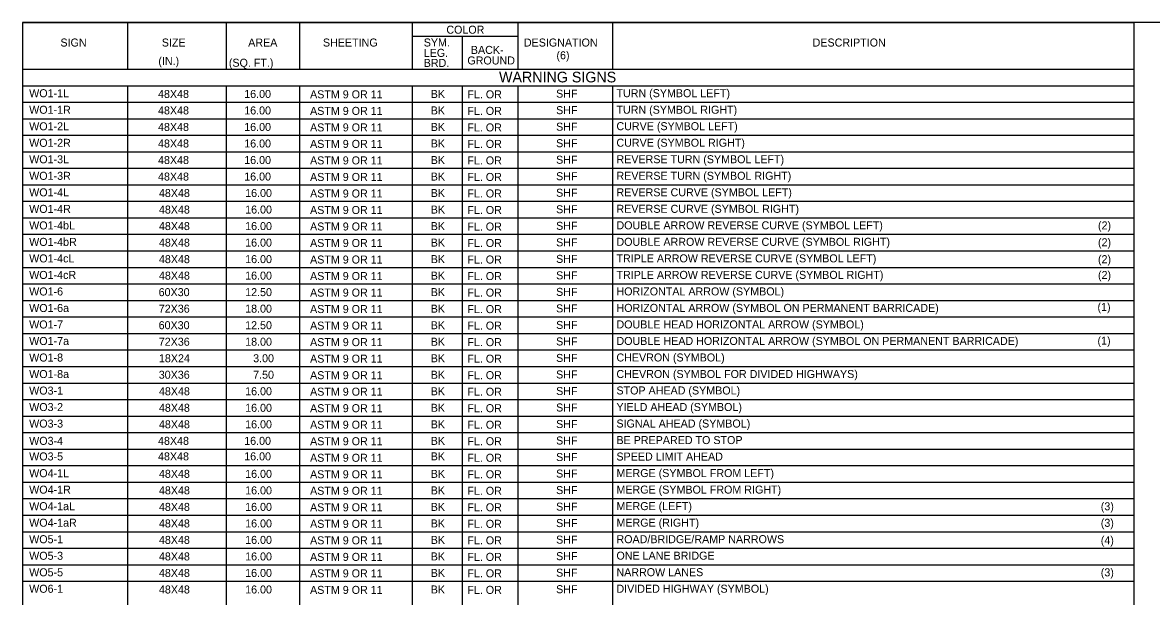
# Model space of a CAD drawing. Extents: x -439.1 to -407.9, y -458.1 to -437.7.
# Drawn here: x -439.11 to -418.9, y -447.95 to -437.68 of the extents above; entities that cross this region are included whole.
import ezdxf

# ---------------------------------------------------------------- set-up
doc = ezdxf.new("R2010")
doc.units = 0
for name, color, linetype in [('Draft_Named_Boundary', 7, 'Continuous'), ('Level 4', 7, 'Continuous'), ('Level 45', 7, 'Continuous')]:
    doc.layers.add(name, color=color, linetype=linetype)

msp = doc.modelspace()

# ---------------------------------------------------------------- linework, layer by layer
at = {"layer": 'Draft_Named_Boundary'}
msp.add_lwpolyline([(-439.109, -458.051), (-407.859, -458.051), (-407.859, -437.676), (-439.109, -437.676)], close=True, dxfattribs=at)
at = {"layer": 'Level 4'}
for p, q in [((-439.109, -437.676), (-419.212, -437.676)), ((-439.109, -437.676), (-439.109, -458.051)), ((-437.233, -437.676), (-437.233, -438.508)), ((-435.462, -437.676), (-435.462, -438.508)), ((-434.152, -437.676), (-434.152, -438.508)), ((-432.136, -437.676), (-432.136, -438.508)), ((-430.244, -437.676), (-430.244, -438.508)), ((-428.547, -437.676), (-428.547, -438.508)), ((-419.212, -437.676), (-419.212, -458.051)), ((-432.136, -437.921), (-430.244, -437.921)), ((-431.24, -437.921), (-431.24, -438.508)), ((-439.109, -438.508), (-419.212, -438.508)), ((-439.109, -438.806), (-419.212, -438.806)), ((-437.233, -438.806), (-437.233, -458.051)), ((-435.462, -438.806), (-435.462, -458.051)), ((-434.152, -438.806), (-434.152, -458.051)), ((-432.136, -438.806), (-432.136, -458.051)), ((-431.24, -438.806), (-431.24, -458.051)), ((-430.244, -438.806), (-430.244, -458.051)), ((-428.547, -438.806), (-428.547, -458.051)), ((-439.109, -439.102), (-419.212, -439.102)), ((-439.109, -439.398), (-419.212, -439.398)), ((-439.109, -439.693), (-419.212, -439.693)), ((-439.109, -439.989), (-419.212, -439.989)), ((-439.109, -440.285), (-419.212, -440.285)), ((-439.109, -440.581), (-419.212, -440.581)), ((-439.109, -440.877), (-419.212, -440.877)), ((-439.109, -441.173), (-419.212, -441.173)), ((-439.109, -441.468), (-419.212, -441.468)), ((-439.109, -441.764), (-419.212, -441.764)), ((-439.109, -442.06), (-419.212, -442.06)), ((-439.109, -442.356), (-419.212, -442.356)), ((-439.109, -442.652), (-419.212, -442.652)), ((-439.109, -442.947), (-419.212, -442.947)), ((-439.109, -443.243), (-419.212, -443.243)), ((-439.109, -443.539), (-419.212, -443.539)), ((-439.109, -443.835), (-419.212, -443.835)), ((-439.109, -444.131), (-419.212, -444.131)), ((-439.109, -444.426), (-419.212, -444.426)), ((-439.109, -444.722), (-419.212, -444.722)), ((-439.109, -445.018), (-419.212, -445.018)), ((-439.109, -445.314), (-419.212, -445.314)), ((-439.109, -445.61), (-419.212, -445.61)), ((-439.109, -445.905), (-419.212, -445.905)), ((-439.109, -446.201), (-419.212, -446.201)), ((-439.109, -446.497), (-419.212, -446.497)), ((-439.109, -446.793), (-419.212, -446.793)), ((-439.109, -447.089), (-419.212, -447.089)), ((-439.109, -447.384), (-419.212, -447.384)), ((-439.109, -447.68), (-419.212, -447.68))]:
    msp.add_line(p, q, dxfattribs=at)

# ---------------------------------------------------------------- texts
for s, height, p in [('COLOR', 0.1431, (-431.522, -437.875)), ('SIGN', 0.1433, (-438.431, -438.105)), ('SIZE', 0.1433, (-436.616, -438.105)), ('AREA', 0.1433, (-435.07, -438.105)), ('SHEETING', 0.1433, (-433.732, -438.105)), ('SYM.', 0.1433, (-431.927, -438.104)), ('LEG.', 0.1433, (-431.927, -438.29)), ('BACK-', 0.1433, (-431.083, -438.237)), ('DESIGNATION', 0.14328, (-430.134, -438.105)), ('DESCRIPTION', 0.14328, (-424.965, -438.105)), ('BRD.', 0.1433, (-431.927, -438.47)), ('GROUND', 0.1433, (-431.146, -438.426)), ('(6)', 0.1433, (-429.551, -438.333)), ('WARNING SIGNS', 0.19076, (-430.579, -438.747)), ('WO1-1L', 0.1433, (-438.991, -439.013)), ('ASTM 9 OR 11', 0.14328, (-433.962, -439.033)), ('BK', 0.1433, (-431.802, -439.026)), ('FL. OR', 0.1433, (-431.146, -439.033)), ('SHF', 0.1433, (-429.557, -439.02)), ('TURN (SYMBOL LEFT) ', 0.14328, (-428.477, -439.012)), ('WO1-1R', 0.1433, (-438.991, -439.309)), ('ASTM 9 OR 11', 0.14328, (-433.962, -439.329)), ('BK', 0.1433, (-431.802, -439.321)), ('FL. OR', 0.1433, (-431.146, -439.329)), ('SHF', 0.1433, (-429.557, -439.316)), ('TURN (SYMBOL RIGHT)', 0.14328, (-428.477, -439.308)), ('WO1-2L', 0.1433, (-438.991, -439.605)), ('ASTM 9 OR 11', 0.14328, (-433.962, -439.625)), ('BK', 0.1433, (-431.802, -439.617)), ('FL. OR', 0.1433, (-431.146, -439.625)), ('SHF', 0.1433, (-429.557, -439.612)), ('CURVE (SYMBOL LEFT) ', 0.14328, (-428.477, -439.603)), ('WO1-2R', 0.1433, (-438.991, -439.901)), ('CURVE (SYMBOL RIGHT) ', 0.14328, (-428.477, -439.899)), ('ASTM 9 OR 11', 0.14328, (-433.962, -439.92)), ('BK', 0.1433, (-431.802, -439.913)), ('FL. OR', 0.1433, (-431.146, -439.92)), ('SHF', 0.1433, (-429.557, -439.908)), ('WO1-3L', 0.1433, (-438.991, -440.196)), ('ASTM 9 OR 11', 0.14328, (-433.962, -440.216)), ('BK', 0.1433, (-431.802, -440.209)), ('FL. OR', 0.1433, (-431.146, -440.216)), ('SHF', 0.1433, (-429.557, -440.204)), ('REVERSE TURN (SYMBOL LEFT) ', 0.14328, (-428.477, -440.195)), ('WO1-3R', 0.1433, (-438.991, -440.492)), ('ASTM 9 OR 11', 0.14328, (-433.962, -440.512)), ('BK', 0.1433, (-431.802, -440.505)), ('FL. OR', 0.1433, (-431.146, -440.512)), ('SHF', 0.1433, (-429.557, -440.499)), ('REVERSE TURN (SYMBOL RIGHT) ', 0.14328, (-428.477, -440.491)), ('WO1-4L', 0.1433, (-438.991, -440.788)), ('ASTM 9 OR 11', 0.14328, (-433.962, -440.808)), ('BK', 0.1433, (-431.802, -440.8)), ('FL. OR', 0.1433, (-431.146, -440.808)), ('SHF', 0.1433, (-429.557, -440.795)), ('REVERSE CURVE (SYMBOL LEFT) ', 0.14328, (-428.477, -440.787)), ('WO1-4R', 0.1433, (-438.991, -441.084)), ('ASTM 9 OR 11', 0.14328, (-433.962, -441.104)), ('BK', 0.1433, (-431.802, -441.096)), ('FL. OR', 0.1433, (-431.146, -441.104)), ('SHF', 0.1433, (-429.557, -441.091)), ('REVERSE CURVE (SYMBOL RIGHT) ', 0.14328, (-428.477, -441.083)), ('WO1-4bL', 0.1433, (-438.991, -441.38)), ('ASTM 9 OR 11', 0.14328, (-433.962, -441.399)), ('BK', 0.1433, (-431.802, -441.392)), ('FL. OR', 0.1433, (-431.146, -441.4)), ('SHF', 0.1433, (-429.557, -441.387)), ('DOUBLE ARROW REVERSE CURVE (SYMBOL LEFT) ', 0.14328, (-428.477, -441.378)), ('(2)', 0.1433, (-419.856, -441.38)), ('WO1-4bR', 0.1433, (-438.991, -441.675)), ('ASTM 9 OR 11', 0.14328, (-433.962, -441.695)), ('BK', 0.1433, (-431.802, -441.688)), ('FL. OR', 0.1433, (-431.146, -441.695)), ('SHF', 0.1433, (-429.557, -441.683)), ('DOUBLE ARROW REVERSE CURVE (SYMBOL RIGHT) ', 0.14328, (-428.477, -441.674)), ('(2)', 0.1433, (-419.856, -441.682)), ('WO1-4cL', 0.1433, (-438.991, -441.971)), ('ASTM 9 OR 11', 0.14328, (-433.962, -441.991)), ('BK', 0.1433, (-431.802, -441.984)), ('FL. OR', 0.1433, (-431.146, -441.991)), ('SHF', 0.1433, (-429.557, -441.979)), ('TRIPLE ARROW REVERSE CURVE (SYMBOL LEFT) ', 0.14328, (-428.477, -441.97)), ('(2)', 0.1433, (-419.856, -441.985)), ('WO1-4cR', 0.1433, (-438.991, -442.267)), ('ASTM 9 OR 11', 0.14328, (-433.962, -442.287)), ('BK', 0.1433, (-431.802, -442.279)), ('FL. OR', 0.1433, (-431.146, -442.287)), ('SHF', 0.1433, (-429.557, -442.274)), ('TRIPLE ARROW REVERSE CURVE (SYMBOL RIGHT) ', 0.14328, (-428.477, -442.266)), ('(2)', 0.1433, (-419.856, -442.268)), ('WO1-6', 0.1433, (-438.991, -442.563)), ('ASTM 9 OR 11', 0.14328, (-433.962, -442.583)), ('BK', 0.1433, (-431.802, -442.575)), ('FL. OR', 0.1433, (-431.146, -442.583)), ('SHF', 0.1433, (-429.557, -442.57)), ('HORIZONTAL ARROW (SYMBOL)', 0.14328, (-428.477, -442.562)), ('WO1-6a', 0.1433, (-438.991, -442.859)), ('ASTM 9 OR 11', 0.14328, (-433.962, -442.878)), ('BK', 0.1433, (-431.802, -442.871)), ('FL. OR', 0.1433, (-431.146, -442.879)), ('SHF', 0.1433, (-429.557, -442.866)), ('HORIZONTAL ARROW (SYMBOL ON PERMANENT BARRICADE)', 0.14328, (-428.477, -442.857)), ('(1)', 0.1433, (-419.865, -442.84)), ('WO1-7', 0.1433, (-438.991, -443.154)), ('ASTM 9 OR 11', 0.14328, (-433.962, -443.174)), ('BK', 0.1433, (-431.802, -443.167)), ('FL. OR', 0.1433, (-431.146, -443.174)), ('SHF', 0.1433, (-429.557, -443.162)), ('DOUBLE HEAD HORIZONTAL ARROW (SYMBOL)', 0.14328, (-428.477, -443.153)), ('WO1-7a', 0.1433, (-438.991, -443.45)), ('ASTM 9 OR 11', 0.14328, (-433.962, -443.47)), ('BK', 0.1433, (-431.802, -443.463)), ('FL. OR', 0.1433, (-431.146, -443.47)), ('SHF', 0.1433, (-429.557, -443.458)), ('DOUBLE HEAD HORIZONTAL ARROW (SYMBOL ON PERMANENT BARRICADE)', 0.14328, (-428.477, -443.449)), ('(1)', 0.1433, (-419.865, -443.444)), ('WO1-8', 0.1433, (-438.991, -443.746)), ('CHEVRON (SYMBOL)', 0.14328, (-428.477, -443.745)), ('ASTM 9 OR 11', 0.14328, (-433.962, -443.766)), ('BK', 0.1433, (-431.802, -443.759)), ('FL. OR', 0.1433, (-431.146, -443.766)), ('SHF', 0.1433, (-429.557, -443.753)), ('WO1-8a', 0.1433, (-438.991, -444.042)), ('ASTM 9 OR 11', 0.14328, (-433.962, -444.062)), ('BK', 0.1433, (-431.802, -444.054)), ('FL. OR', 0.1433, (-431.146, -444.062)), ('SHF', 0.1433, (-429.557, -444.049)), ('CHEVRON (SYMBOL FOR DIVIDED HIGHWAYS)', 0.14328, (-428.477, -444.041)), ('WO3-1', 0.1433, (-438.991, -444.338)), ('BK', 0.1433, (-431.802, -444.35)), ('SHF', 0.1433, (-429.557, -444.345)), ('STOP AHEAD (SYMBOL) ', 0.14328, (-428.477, -444.336)), ('ASTM 9 OR 11', 0.14328, (-433.962, -444.357)), ('FL. OR', 0.1433, (-431.146, -444.358)), ('WO3-2', 0.1433, (-438.991, -444.633)), ('ASTM 9 OR 11', 0.14328, (-433.962, -444.653)), ('BK', 0.1433, (-431.802, -444.646)), ('FL. OR', 0.1433, (-431.146, -444.653)), ('SHF', 0.1433, (-429.557, -444.641)), ('YIELD AHEAD (SYMBOL) ', 0.14328, (-428.477, -444.632)), ('WO3-3 ', 0.1433, (-438.991, -444.929)), ('ASTM 9 OR 11', 0.14328, (-433.962, -444.949)), ('BK', 0.1433, (-431.802, -444.942)), ('FL. OR', 0.1433, (-431.146, -444.949)), ('SHF', 0.1433, (-429.557, -444.937)), ('SIGNAL AHEAD (SYMBOL)', 0.14328, (-428.477, -444.928)), ('WO3-4', 0.1433, (-438.991, -445.238)), ('ASTM 9 OR 11', 0.14328, (-433.962, -445.245)), ('BK', 0.1433, (-431.802, -445.238)), ('FL. OR', 0.1433, (-431.146, -445.245)), ('SHF', 0.1433, (-429.557, -445.232)), ('BE PREPARED TO STOP ', 0.14328, (-428.477, -445.224)), ('WO3-5', 0.1433, (-438.991, -445.517)), ('ASTM 9 OR 11', 0.14328, (-433.962, -445.541)), ('BK', 0.1433, (-431.802, -445.516)), ('FL. OR', 0.1433, (-431.146, -445.541)), ('SHF', 0.1433, (-429.557, -445.528)), ('SPEED LIMIT AHEAD ', 0.14328, (-428.477, -445.519)), ('WO4-1L ', 0.1433, (-438.991, -445.817)), ('ASTM 9 OR 11', 0.14328, (-433.962, -445.837)), ('BK', 0.1433, (-431.802, -445.829)), ('FL. OR', 0.1433, (-431.146, -445.837)), ('SHF', 0.1433, (-429.557, -445.824)), ('MERGE (SYMBOL FROM LEFT)', 0.14328, (-428.477, -445.815)), ('WO4-1R ', 0.1433, (-438.991, -446.112)), ('ASTM 9 OR 11', 0.14328, (-433.962, -446.132)), ('BK', 0.1433, (-431.802, -446.125)), ('FL. OR', 0.1433, (-431.146, -446.132)), ('SHF', 0.1433, (-429.557, -446.12)), ('MERGE (SYMBOL FROM RIGHT)', 0.14328, (-428.477, -446.111)), ('WO4-1aL', 0.1433, (-438.991, -446.408)), ('ASTM 9 OR 11', 0.14328, (-433.962, -446.428)), ('BK', 0.1433, (-431.802, -446.421)), ('FL. OR', 0.1433, (-431.146, -446.428)), ('SHF', 0.1433, (-429.557, -446.416)), ('MERGE (LEFT)', 0.14328, (-428.477, -446.407)), ('(3)', 0.1433, (-419.806, -446.41)), ('WO4-1aR', 0.1433, (-438.991, -446.704)), ('ASTM 9 OR 11', 0.14328, (-433.962, -446.724)), ('BK', 0.1433, (-431.802, -446.717)), ('FL. OR', 0.1433, (-431.146, -446.724)), ('SHF', 0.1433, (-429.557, -446.711)), ('MERGE (RIGHT)', 0.14328, (-428.477, -446.703)), ('(3)', 0.1433, (-419.806, -446.706)), ('WO5-1 ', 0.1433, (-438.991, -447)), ('ASTM 9 OR 11', 0.14328, (-433.962, -447.02)), ('BK', 0.1433, (-431.802, -447.012)), ('FL. OR', 0.1433, (-431.146, -447.02)), ('SHF', 0.1433, (-429.557, -447.007)), ('ROAD/BRIDGE/RAMP NARROWS ', 0.14328, (-428.477, -446.999)), ('(4)', 0.1433, (-419.806, -447.018)), ('WO5-3 ', 0.1433, (-438.991, -447.296)), ('ASTM 9 OR 11', 0.14328, (-433.962, -447.316)), ('BK', 0.1433, (-431.802, -447.308)), ('FL. OR', 0.1433, (-431.146, -447.316)), ('SHF', 0.1433, (-429.557, -447.303)), ('ONE LANE BRIDGE', 0.14328, (-428.477, -447.294)), ('WO5-5', 0.1433, (-438.991, -447.592)), ('ASTM 9 OR 11', 0.14328, (-433.962, -447.611)), ('BK', 0.1433, (-431.802, -447.604)), ('FL. OR', 0.1433, (-431.146, -447.611)), ('SHF', 0.1433, (-429.557, -447.599)), ('NARROW LANES ', 0.14328, (-428.477, -447.59)), ('(3)', 0.1433, (-419.806, -447.593)), ('WO6-1 ', 0.1433, (-438.991, -447.887)), ('ASTM 9 OR 11', 0.14328, (-433.962, -447.907)), ('BK', 0.1433, (-431.802, -447.9)), ('FL. OR', 0.1433, (-431.146, -447.907)), ('SHF', 0.1433, (-429.557, -447.895)), ('DIVIDED HIGHWAY (SYMBOL)', 0.14328, (-428.477, -447.886))]:
    msp.add_text(s, height=height, dxfattribs=at).set_placement(p)
at = {"layer": 'Level 45'}
for s, p in [('(IN.)', (-436.678, -438.436)), ('(SQ. FT.)', (-435.416, -438.467)), ('48X48', (-436.684, -439.026)), ('16.00', (-435.141, -439.026)), ('48X48', (-436.684, -439.321)), ('16.00', (-435.141, -439.321)), ('48X48', (-436.684, -439.617)), ('16.00', (-435.141, -439.617)), ('48X48', (-436.684, -439.913)), ('16.00', (-435.141, -439.913)), ('48X48', (-436.684, -440.209)), ('16.00', (-435.141, -440.209)), ('48X48', (-436.684, -440.505)), ('16.00', (-435.141, -440.505)), ('48X48', (-436.668, -440.8)), ('16.00', (-435.124, -440.8)), ('48X48', (-436.668, -441.096)), ('16.00', (-435.124, -441.096)), ('48X48', (-436.668, -441.392)), ('16.00', (-435.124, -441.392)), ('48X48', (-436.668, -441.688)), ('16.00', (-435.124, -441.688)), ('48X48', (-436.668, -441.984)), ('16.00', (-435.124, -441.984)), ('48X48', (-436.668, -442.279)), ('16.00', (-435.124, -442.279)), ('60X30', (-436.673, -442.575)), ('12.50', (-435.124, -442.575)), ('72X36', (-436.671, -442.871)), ('18.00', (-435.124, -442.871)), ('60X30', (-436.673, -443.167)), ('12.50', (-435.124, -443.167)), ('72X36', (-436.671, -443.463)), ('18.00', (-435.124, -443.463)), ('18X24', (-436.668, -443.759)), ('3.00', (-434.981, -443.759)), ('30X36', (-436.671, -444.054)), ('7.50', (-434.981, -444.054)), ('48X48', (-436.668, -444.35)), ('16.00', (-435.124, -444.35)), ('48X48', (-436.668, -444.646)), ('16.00', (-435.124, -444.646)), ('48X48', (-436.668, -444.942)), ('16.00', (-435.124, -444.942)), ('48X48', (-436.684, -445.238)), ('16.00', (-435.141, -445.238)), ('48X48', (-436.684, -445.516)), ('16.00', (-435.141, -445.516)), ('48X48', (-436.668, -445.829)), ('16.00', (-435.124, -445.829)), ('48X48', (-436.668, -446.125)), ('16.00', (-435.124, -446.125)), ('48X48', (-436.668, -446.421)), ('16.00', (-435.124, -446.421)), ('48X48', (-436.668, -446.717)), ('16.00', (-435.124, -446.717)), ('48X48', (-436.668, -447.012)), ('16.00', (-435.124, -447.012)), ('48X48', (-436.668, -447.308)), ('16.00', (-435.124, -447.308)), ('48X48', (-436.668, -447.604)), ('16.00', (-435.124, -447.604)), ('48X48', (-436.668, -447.9)), ('16.00', (-435.124, -447.9))]:
    msp.add_text(s, height=0.1433, dxfattribs=at).set_placement(p)

doc.saveas('drawing.dxf')
